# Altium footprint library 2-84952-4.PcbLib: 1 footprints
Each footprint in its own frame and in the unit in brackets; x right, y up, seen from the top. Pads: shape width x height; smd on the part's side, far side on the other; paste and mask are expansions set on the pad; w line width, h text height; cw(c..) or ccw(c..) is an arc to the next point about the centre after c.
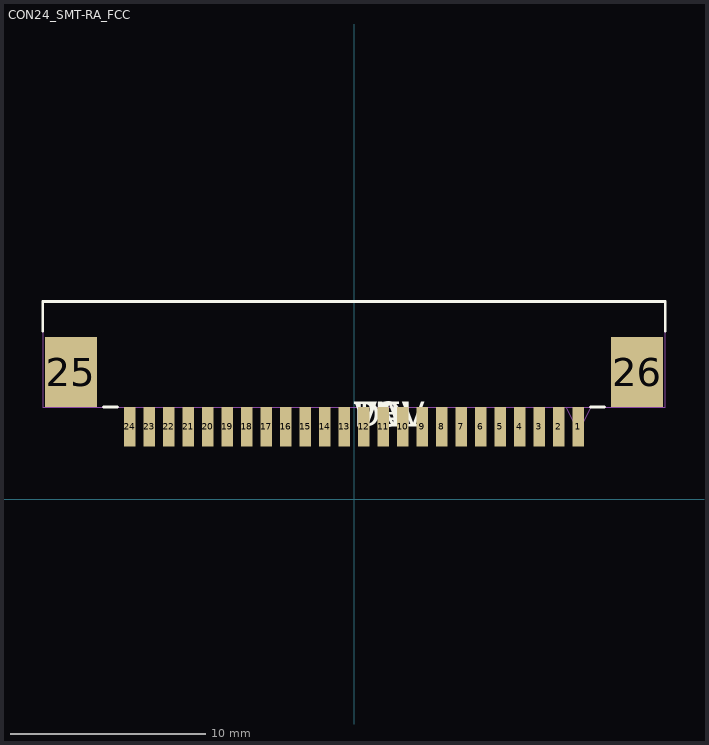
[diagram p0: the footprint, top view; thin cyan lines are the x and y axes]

## CON24_SMT-RA_FCC [mil]
pads (26):
  rect 24x79 smd: 1(452.76,146) 2(413.39,146) 3(374.02,146) 4(334.65,146) 5(295.28,146) 6(255.91,146) 7(216.54,146) 8(177.17,146) 9(137.8,146) 10(98.43,146) 11(59.06,146) 12(19.68,146) 13(-19.69,146) 14(-59.06,146) 15(-98.43,146) 16(-137.8,146) 17(-177.17,146) 18(-216.54,146) 19(-255.91,146) 20(-295.28,146) 21(-334.65,146) 22(-374.02,146) 23(-413.39,146) 24(-452.76,146)
  rect 105x142 smd: 25(-571.5,256.5) 26(571.5,256.5)
Top Overlay:
  lines w6: -628.5,339.8 -628.5,398.5 628.5,398.5 628.5,339.8 ; -505.9,185.5 -477.86,185.5 ; 477.86,185.5 505.9,185.5
  text "PN" at 0,146 h50
  text "DEV" at 0,146 h50
  text "VAL" at 0,146 h50
  text "TOL" at 0,146 h50
Mechanical 1:
  lines w0: 427.76,185.5 452.76,135.5 477.76,185.5 ; -628.5,185.5 628.5,185.5 628.5,398.5 -628.5,398.5 -628.5,185.5
  text "RefDes2" at 0,146 h50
